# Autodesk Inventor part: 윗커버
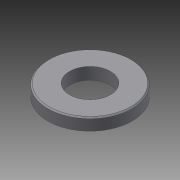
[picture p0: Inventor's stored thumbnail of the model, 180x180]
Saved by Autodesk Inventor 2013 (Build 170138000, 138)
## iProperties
Created: 2023-03
Part Number: 윗커버
Material: 알루미늄 6061
Document SubType Name: Modeling
Designer: mdu-01
Density: 1 g/cm^3
Author: mdu-01
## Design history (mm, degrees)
sketch "스케치1"
  geometry: C1 r 35 at (0, 0) reference; C2 r 21.5 at (0, 0) reference; C3 r 17 at (0, 0); 1 further point
  constraints: 1 centre point
  dimensions: "d0" = 34 diameter of C3
extrude "돌출1" new body sketch "스케치1" distance "d2" = 10; taper "d3" = 0 deg
chamfer "모따기1" distance "d4" = 1; stored, may be unused: second distance "d5" = 2, angle "d6" = 45 deg
sketch "스케치2" dims "d7" = 52
  geometry: 3 further points
  constraints: 2 vertical alignment, 1 coincident, 2 other
hole "구멍1" sketch "스케치2" at (0, 26) diameter "d9" = 4.5; stored, may be unused: countersink angle "d13" = 90 deg, drill point angle "d15" = 118 deg; dims "d10" = 6, "d11" = 8, "d12" = 4.6, "d14" = 8
node "솔리드1"
pattern_circular "원형 패턴1" dims angle "d17" = 360 deg
node "참조1"
node "참조2"
